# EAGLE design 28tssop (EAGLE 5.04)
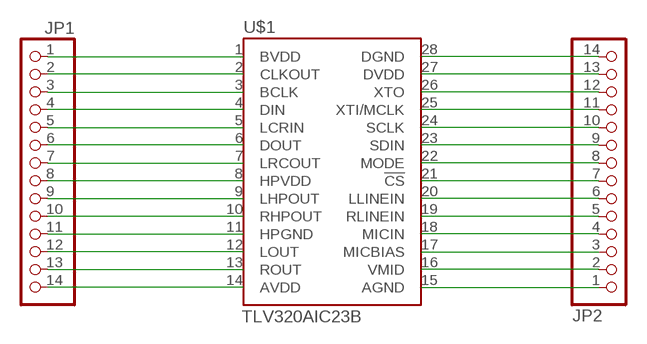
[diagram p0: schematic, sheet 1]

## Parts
JP1  PINHD-1X14  [1X14]
JP2  PINHD-1X14  [1X14]
U$1  TLV320AIC23B  [TSSOP28]

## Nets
N$1: JP1.1 U$1.1(BVDD)
N$2: JP1.2 U$1.2(CLKOUT)
N$3: JP1.3 U$1.3(BCLK)
N$4: JP1.4 U$1.4(DIN)
N$5: JP1.5 U$1.5(LCRIN)
N$6: JP1.6 U$1.6(DOUT)
N$7: JP1.7 U$1.7(LRCOUT)
N$8: JP1.8 U$1.8(HPVDD)
N$9: JP1.9 U$1.9(LHPOUT)
N$10: JP1.10 U$1.10(RHPOUT)
N$11: JP1.11 U$1.11(HPGND)
N$12: JP1.12 U$1.12(LOUT)
N$13: JP1.13 U$1.13(ROUT)
N$14: JP1.14 U$1.14(AVDD)
N$15: JP2.1 U$1.15(AGND)
N$16: JP2.2 U$1.16(VMID)
N$17: JP2.3 U$1.17(MICBIAS)
N$18: JP2.4 U$1.18(MICIN)
N$19: JP2.5 U$1.19(RLINEIN)
N$20: JP2.6 U$1.20(LLINEIN)
N$21: JP2.7 U$1.21(!CS)
N$22: JP2.8 U$1.22(MODE)
N$23: JP2.9 U$1.23(SDIN)
N$24: JP2.10 U$1.24(SCLK)
N$25: JP2.11 U$1.25(XTI/MCLK)
N$26: JP2.12 U$1.26(XTO)
N$27: JP2.13 U$1.27(DVDD)
N$28: JP2.14 U$1.28(DGND)

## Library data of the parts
JP1 JP2 = pinhead:PINHD-1X14: PIN HEADER
U$1 = trl:TLV320AIC23B

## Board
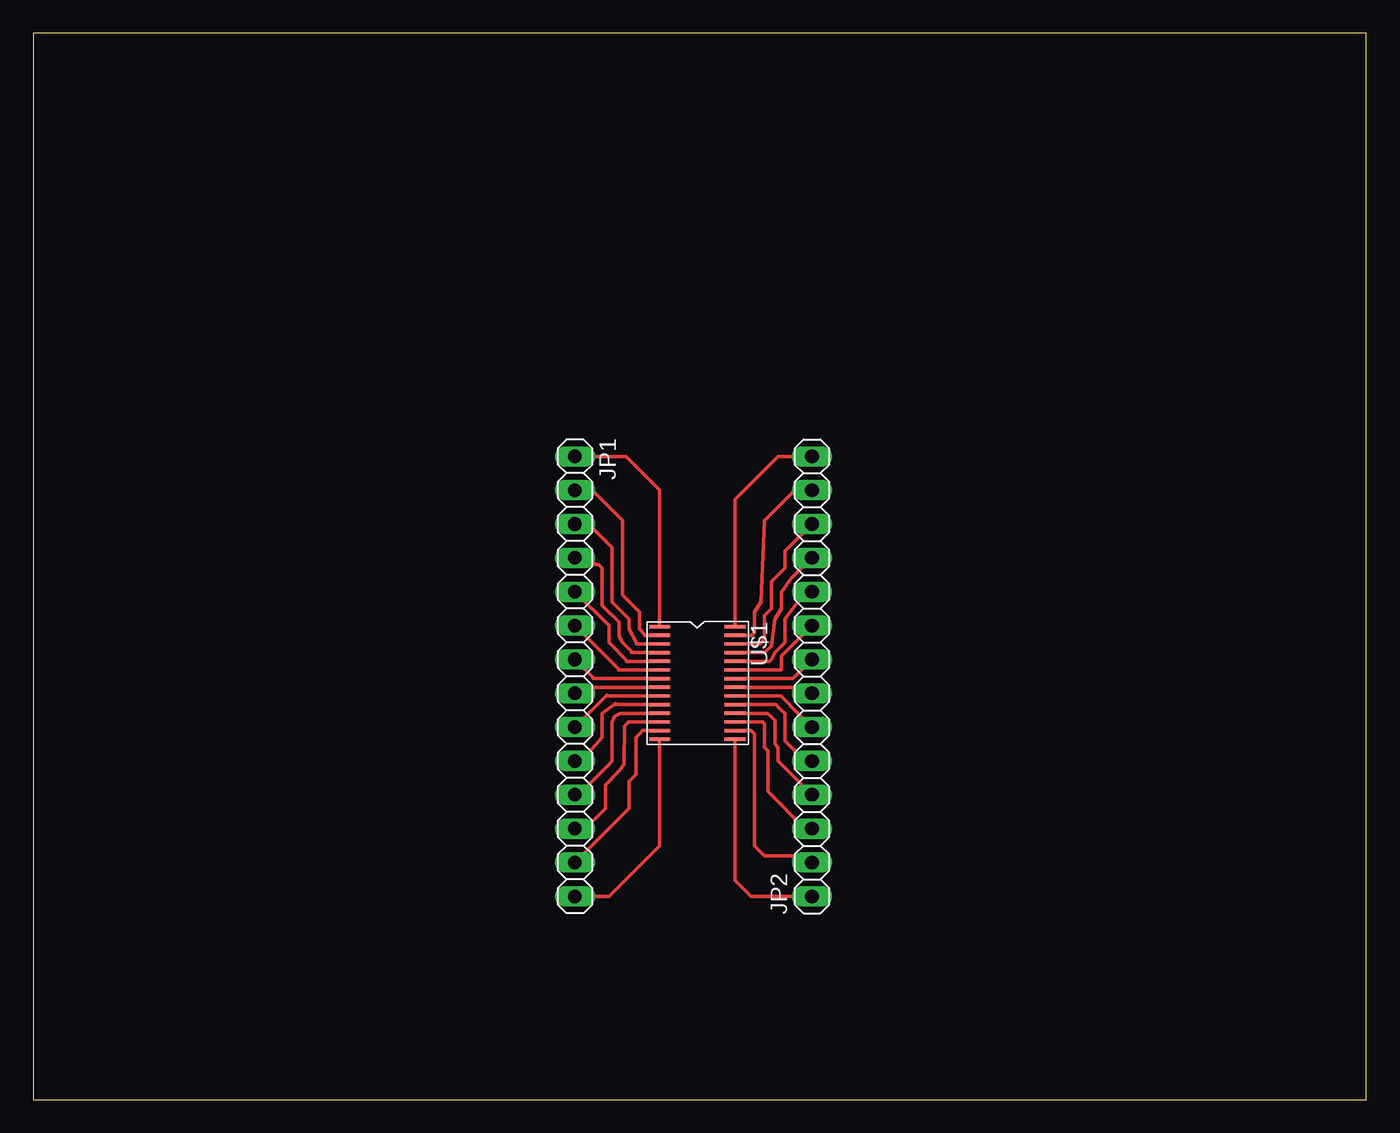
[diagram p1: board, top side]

Size 100 x 80 mm. Coordinates in mm from the lower left corner, seen from the top.
Outline: 0,0 100,0 100,80 0,80 0,0
Copper layers (1*16): Top 0.035mm / dielectric 1.5mm / Bottom 0.035mm
Design rules "default": minimum track width 10mil, minimum drill 24mil, track to track 8mil, track to pad 8mil, pad to pad 8mil, via to via 8mil, smd to smd 8mil, copper to edge 40mil, drill to drill 8mil, minimum pad ring 10mil, minimum via ring 8mil, stop-mask expansion 4mil, vias tented up to drill 0mil, thermal gap 10mil

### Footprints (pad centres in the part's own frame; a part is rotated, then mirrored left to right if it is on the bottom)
1X14 = drill 1.016 long: 1 -16.51,0; 2 -13.97,0; 3 -11.43,0; 4 -8.89,0; 5 -6.35,0; 6 -3.81,0; 7 -1.27,0; 8 1.27,0; 9 3.81,0; 10 6.35,0; 11 8.89,0; 12 11.43,0; 13 13.97,0; 14 16.51,0
TSSOP28 = smd 0.25 x 1.55: 1 -3.81,-2.54; 2 -3.16,-2.54; 3 -2.51,-2.54; 4 -1.86,-2.54; 5 -1.21,-2.54; 6 -0.56,-2.54; 7 0.09,-2.54; 8 0.74,-2.54; 9 1.39,-2.54; 10 2.04,-2.54; 11 2.69,-2.54; 12 3.34,-2.54; 13 3.99,-2.54; 14 4.64,-2.54; 15 4.64,3.11; 16 3.99,3.11; 17 3.34,3.11; 18 2.69,3.11; 19 2.04,3.11; 20 1.39,3.11; 21 0.74,3.11; 22 0.09,3.11; 23 -0.56,3.11; 24 -1.21,3.11; 25 -1.86,3.11; 26 -2.51,3.11; 27 -3.16,3.11; 28 -3.81,3.11

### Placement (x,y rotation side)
JP1  40.64,31.75 270 top
JP2  58.42,31.75 90 top
U$1  49.53,31.67 270 top

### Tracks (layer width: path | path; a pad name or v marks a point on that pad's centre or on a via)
N$1
  Top 0.254: JP1.1 44.45,48.26 46.99,45.72 U$1.1
N$2
  Top 0.254: JP1.2 41.91,45.72 43.94,43.69 44.2,43.43 44.2,37.85 45.47,36.58 45.47,35.31 45.86,34.91 45.86,34.83 U$1.2
N$3
  Top 0.254: JP1.3 40.89,43.43 41.4,43.43 43.18,41.66 43.43,41.4 43.43,37.34 44.7,36.07 44.7,35.31 45.24,34.26 45.24,34.18 U$1.3
N$4
  Top 0.254: JP1.4 40.89,40.89 41.4,40.89 42.16,40.13 42.42,40.13 42.67,39.88 42.67,37.08 43.94,35.81 43.94,34.8 44.2,34.29 44.88,33.61 44.88,33.53 U$1.4
N$5
  Top 0.254: JP1.5 43.18,35.56 43.18,34.29 44.51,32.96 44.51,32.88 U$1.5
N$6
  Top 0.254: JP1.6 43.18,33.02 43.89,32.31 43.89,32.23 U$1.6
N$7
  Top 0.254: JP1.7 41.91,31.75 42,31.66 42,31.58 U$1.7
N$8
  Top 0.254: JP1.8 41.17,31.01 41.17,30.93 U$1.8
N$9
  Top 0.254: JP1.9 43.06,30.36 43.06,30.28 U$1.9
N$10
  Top 0.254: JP1.10 41.15,25.4 42.67,27.18 42.67,28.96 43.68,29.71 43.68,29.63 U$1.10
N$11
  Top 0.254: JP1.11 40.89,23.11 41.15,23.11 41.66,23.62 43.18,25.15 43.43,25.4 43.43,26.92 43.43,27.18 43.43,28.3 43.6,28.76 44.05,28.98 U$1.11
N$12
  Top 0.254: JP1.12 41.4,20.32 42.93,21.84 42.93,23.62 43.94,24.64 44.3,25.15 44.35,28.04 44.57,28.26 44.67,28.33 U$1.12
N$13
  Top 0.254: JP1.13 44.7,21.84 44.7,23.88 45.21,24.38 45.21,27.18 45.47,27.43 45.72,27.69 | 45.72,27.69 46.92,27.69 | 45.72,27.69 U$1.13
N$14
  Top 0.254: JP1.14 43.18,15.24 46.99,19.05 U$1.14
N$15
  Top 0.254: U$1.15 52.64,16.45 53.85,15.24 JP2.1
N$16
  Top 0.254: U$1.16 53.85,27.68 54.1,27.43 54.1,19.05 54.86,18.29 57.91,18.29 JP2.2
N$17
  Top 0.254: U$1.17 54.73,28.33 54.86,28.19 54.86,26.42 55.12,26.16 55.12,23.11 57.91,20.32 JP2.3
N$18
  Top 0.254: U$1.18 55.09,28.98 55.37,28.7 55.63,28.45 55.63,26.67 55.88,26.42 55.88,25.4 JP2.4
N$19
  Top 0.254: U$1.19 55.71,29.63 55.88,29.46 56.13,29.21 56.39,28.96 56.39,28.45 56.39,26.92 57.91,25.4 JP2.5
N$20
  Top 0.254: U$1.20 56.08,30.28 56.13,30.23 56.39,29.97 57.15,29.21 JP2.6
N$21
  Top 0.254: U$1.21 58.42,30.93 JP2.7
N$22
  Top 0.254: U$1.22 56.98,31.58 JP2.8
N$23
  Top 0.254: U$1.23 56.11,32.23 56.13,32.26 56.13,33.27 JP2.9
N$24
  Top 0.254: U$1.24 55.23,32.88 55.37,33.02 55.63,33.53 56.39,34.29 56.39,36.07 57.15,37.08 57.91,37.85 58.17,37.85 JP2.10
N$25
  Top 0.254: U$1.25 54.86,33.53 55.37,34.04 55.63,36.07 56.13,36.83 56.13,38.1 56.9,39.12 JP2.11
N$26
  Top 0.254: U$1.26 54.5,34.18 54.86,34.54 54.86,36.32 55.37,36.83 55.37,38.86 56.39,39.88 56.39,41.15 JP2.12
N$27
  Top 0.254: U$1.27 53.88,34.83 54.1,35.05 54.1,36.58 54.61,37.34 54.86,43.43 57.15,45.72 JP2.13
N$28
  Top 0.254: U$1.28 52.64,45.02 55.88,48.26 JP2.14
